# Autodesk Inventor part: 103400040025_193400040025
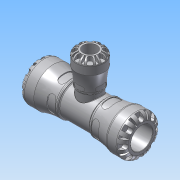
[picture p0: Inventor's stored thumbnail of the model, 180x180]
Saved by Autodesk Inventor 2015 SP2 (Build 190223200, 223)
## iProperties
Created: 2016-12
Part Number: 103400040025_193400040025
Material: PVC-Piping
Description: PLASSON REDUCING TEE 40X25X40 SERIES 1
Document SubType Name: Modeling
Designer: KIM
Mass: 664.223 g
Surface Area: 733.008 cm^2
Volume: 474.445 cm^3
Density: 1.4 g/cm^3
Appearance: Smooth - White
Author: KIM
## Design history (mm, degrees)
derived "1034.ipt"
feature "Solid1::1034.ipt"
tag "TaggingFeature1"
body "Solid1"
other parameters: "d230" = 47, "d231" = 31.25, "d232" = 7.875, "d1" = 29.4, "d8" = 59.5, "d13" = 8, "d14" = 8, "d15" = 0, "d17" = 360 deg, "d19" = 8 deg, "d20" = 0.8, "d21" = 0.8, "d22" = 8 deg, "d24" = 0, "d26" = 360 deg, "d33" = 7, "d43" = 54.6, "d51" = 0.7, "d54" = 14, "d55" = 8.8, "d57" = 15.68, "d58" = 0, "d74" = 0, "d77" = 3.33333, "d79" = 54.6, "d80" = 192, "d82" = 0.8, "d115" = 360 deg, "d139" = 8, "d140" = 0, "d142" = 360 deg, "d207" = 90 deg, "d209" = 20.58, "d210" = 25, "d211" = 31.25, "d212" = 47, "d213" = 39.95, "d215" = 36.66, "d216" = 2.08333, "d217" = 49, "d225" = 86, "d226" = 49, "d228" = 11.9, "d229" = 6.3, "d233" = 6.3, "d234" = 0, "d236" = 360 deg, "d238" = 8 deg, "d239" = 8 deg, "d240" = 0.8, "d241" = 0.8, "d243" = 0, "d245" = 360 deg, "d247" = 1.4, "d248" = 4.2, "d249" = 2.94, "d250" = 7.4375, "d252" = 8.75, "d253" = 5.75, "d254" = 15.68, "d255" = 0, "d257" = 360 deg, "d259" = 0.8, "d261" = 0, "d262" = 1.4, "d264" = 0, "d266" = 0, "d267" = 0.7, "A_" = 86, "H_" = 192, "d_1" = 25, "E_1" = 47, "l_1" = 49
